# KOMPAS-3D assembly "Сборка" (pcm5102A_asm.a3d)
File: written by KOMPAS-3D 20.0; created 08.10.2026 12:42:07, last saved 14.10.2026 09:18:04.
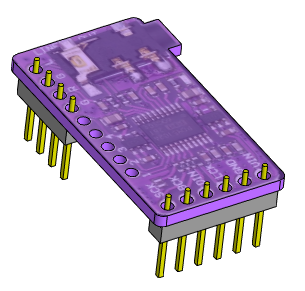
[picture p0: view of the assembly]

Document properties: Полное имя файла: D:\myProjects\Progect_esp32\box_compas\цап ацп\pcm5102A_asm.a3d

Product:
- Part/product: Сборка
    Масса: 0.00743997
  - Component [detail]: Деталь  | Масса: 0.000521406; source file: ..\разъемы\pls_4.m3d
  - Component [detail]: Деталь  | Масса: 0.00078211; source file: ..\разъемы\pls_6.m3d
  - Component [detail]: Деталь  | Масса: 0.00613645; source file: pcm5102A.m3d

Referenced files in D:\myProjects\Progect_esp32\box_compas\цап ацп\: pcm5102A.m3d
Referenced files in D:\myProjects\Progect_esp32\box_compas\разъемы\: pls_6.m3d, pls_4.m3d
